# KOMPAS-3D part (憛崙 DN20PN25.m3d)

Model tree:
1. Объединить компоненты:1  (labels: СЕНС DN20PN25)

Referenced files in D:\Савин\!СЕНСОР\3D для заказчика\!Новый перечень\СЕНС\1. СЕНС\DN20\: СЕНС DN20PN25.a3d
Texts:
  СЕНС DN20PN25
  ООО НПП Сенсор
